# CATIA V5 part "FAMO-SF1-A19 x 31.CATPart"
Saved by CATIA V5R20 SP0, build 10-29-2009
Part number: FAMO-SF1-A19 x 31
Definition: NONE
Nomenclature: FAMO-SF1-A19 x 31
Source: Unknown
Description: FAMO-SF1-A19 x 31
Bounding box of the stored display mesh (mm): x -13 to 18, y -17 to 17, z -17 to 17
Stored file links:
  C:\Users\Utente\Desktop\IO LAVORO\3D X SITO CF\X SITO\FAMO\FAMO-SF1-A19 x 31.CATPart
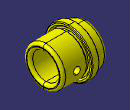
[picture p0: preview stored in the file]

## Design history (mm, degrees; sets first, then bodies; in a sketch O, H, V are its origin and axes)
Body1 "FAMO-SF1-A19 x 31" (main body)
  Solid1: solid without history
